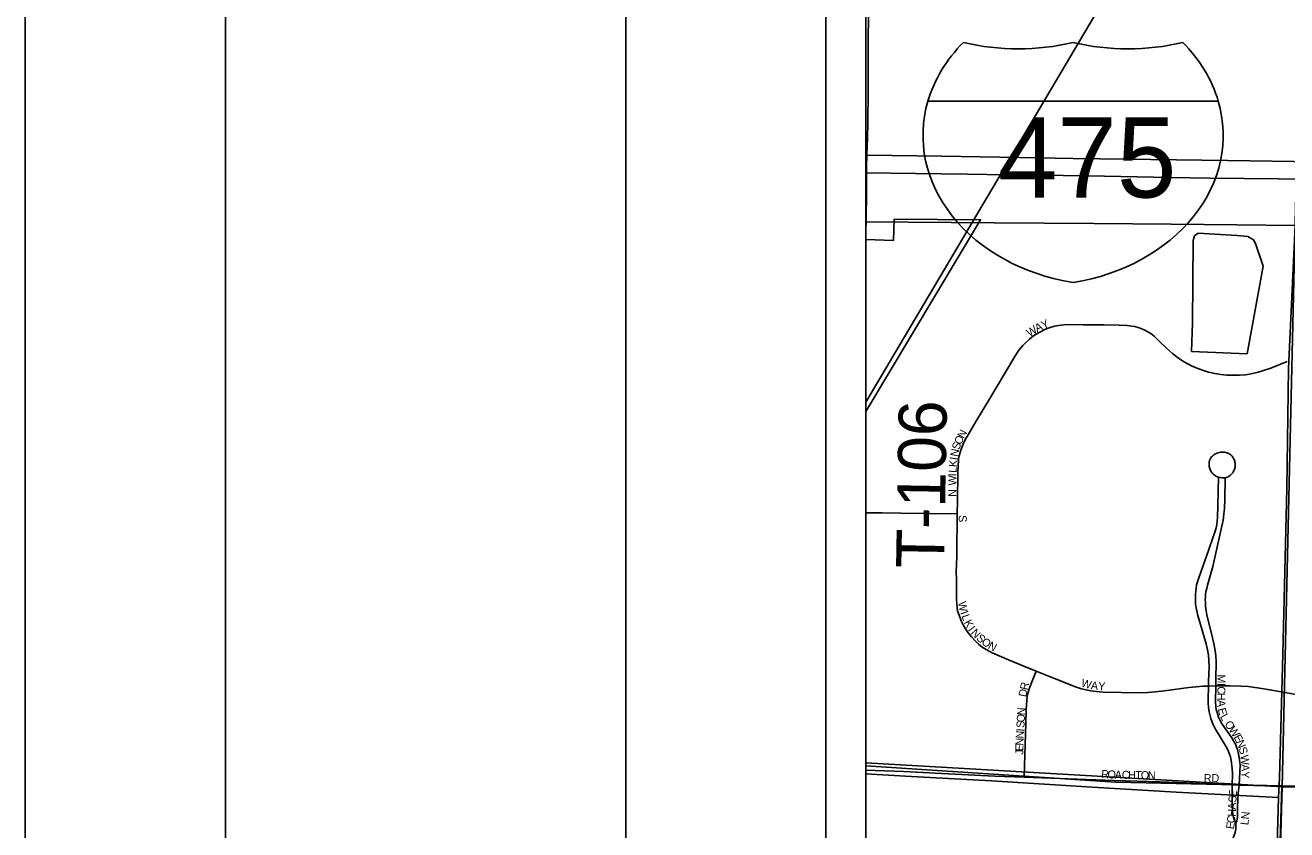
# Model space of a CAD drawing. Extents: x -5.6 to 34, y 0 to 22.
# Drawn here: x 0 to 3.152, y 16.752 to 18.761 of the extents above; entities that cross this region are included whole.
import ezdxf

# ---------------------------------------------------------------- set-up
doc = ezdxf.new("R2010")
doc.units = 0
for name, color, linetype in [('GM_X_City_Street', 7, 'Continuous'), ('GM_X_City_Street_Text', 7, 'Continuous'), ('GM_X_Corporation', 7, 'Continuous'), ('GM_X_County_Road', 7, 'Continuous'), ('GM_X_Interstate_Location', 7, 'Continuous'), ('GM_X_Interstate_Route', 7, 'Continuous'), ('GM_X_Interstate_Shield', 7, 'Continuous'), ('GM_X_Minor_Lake', 7, 'Continuous'), ('GM_X_Minor_River', 7, 'Continuous'), ('GM_X_Rail_Line', 7, 'Continuous'), ('GM_X_Section', 7, 'Continuous'), ('GM_X_Township', 7, 'Continuous'), ('GM_X_Township_Road', 7, 'Continuous'), ('GM_X_Township_Road_Text', 7, 'Continuous'), ('SH_Border', 7, 'Continuous'), ('SH_Cut_Line', 7, 'Continuous'), ('SH_Data', 7, 'Continuous')]:
    doc.layers.add(name, color=color, linetype=linetype)

msp = doc.modelspace()

# ---------------------------------------------------------------- linework, layer by layer
at = {"layer": 'GM_X_City_Street'}
for points in [[(2.1056, 18.6334), (2.1057, 18.6718), (2.1062, 18.7298), (2.107, 18.7758), (2.1077, 18.8077), (2.1078, 18.8277)], [(2.1038, 18.4756), (2.1046, 18.5206), (2.1054, 18.5934)], [(2.1, 18.2364), (2.1016, 18.3334), (2.1019, 18.3922), (2.102, 18.4075), (2.1027, 18.4361), (2.1036, 18.4614), (2.1038, 18.4756)], [(2.3282, 17.541), (2.3291, 17.5724), (2.3301, 17.6438), (2.3307, 17.6628), (2.3312, 17.6714), (2.3318, 17.6777), (2.3334, 17.6857), (2.3345, 17.6909), (2.3378, 17.7019), (2.3428, 17.7146), (2.3488, 17.7267), (2.3554, 17.738), (2.3739, 17.7697), (2.4126, 17.8329), (2.4438, 17.8858), (2.4749, 17.9378), (2.4826, 17.9494), (2.492, 17.9607), (2.4983, 17.9671), (2.5091, 17.977), (2.5159, 17.9825), (2.5239, 17.9882), (2.5364, 17.9952), (2.5492, 18.0015), (2.5601, 18.0057), (2.5712, 18.009), (2.5813, 18.0111), (2.5942, 18.0126), (2.6085, 18.0132), (2.6426, 18.0129), (2.6952, 18.0124), (2.7332, 18.0118), (2.7528, 18.0108), (2.7644, 18.0096), (2.7719, 18.008), (2.7831, 18.0047), (2.7952, 18), (2.8044, 17.9954), (2.812, 17.9906), (2.82, 17.9842), (2.8312, 17.9733), (2.8514, 17.9543), (2.8661, 17.9411), (2.8775, 17.9321), (2.8895, 17.9237), (2.9009, 17.9169), (2.915, 17.9097), (2.9296, 17.9033), (2.9432, 17.8983), (2.956, 17.8946), (2.9715, 17.8912), (2.9872, 17.8887), (3.0017, 17.8872), (3.0175, 17.8867), (3.0334, 17.8871), (3.0483, 17.888), (3.0629, 17.8902), (3.0797, 17.894), (3.0937, 17.8982), (3.1116, 17.9045), (3.1524, 17.9211)], [(2.9813, 17.6318), (2.9787, 17.6328), (2.9761, 17.634), (2.9733, 17.6355), (2.9709, 17.6369), (2.9686, 17.6388), (2.9668, 17.6405), (2.9651, 17.6426), (2.9636, 17.6445), (2.9623, 17.6466), (2.9612, 17.6488), (2.9601, 17.6511), (2.9591, 17.6536), (2.9584, 17.6561), (2.9578, 17.659), (2.9575, 17.6621), (2.9574, 17.665), (2.9575, 17.6678), (2.958, 17.6708), (2.9587, 17.6734), (2.9596, 17.6758), (2.961, 17.6784), (2.9622, 17.6805), (2.9638, 17.6826), (2.9658, 17.6847), (2.9677, 17.6863), (2.9696, 17.6879), (2.9717, 17.6893), (2.9741, 17.6906), (2.9767, 17.6918), (2.98, 17.6931), (2.9832, 17.6939), (2.9862, 17.6945), (2.9895, 17.6949), (2.993, 17.6949), (2.996, 17.6947), (2.9993, 17.694), (3.002, 17.6931), (3.0044, 17.6922), (3.007, 17.6908), (3.0095, 17.6893), (3.0115, 17.6877), (3.0133, 17.6861), (3.015, 17.6843), (3.0164, 17.6824), (3.0175, 17.6806), (3.0188, 17.6785), (3.0199, 17.6761), (3.0208, 17.6737), (3.0216, 17.6714), (3.0221, 17.6692), (3.0225, 17.6673), (3.0228, 17.6654), (3.0229, 17.6633), (3.0229, 17.6613), (3.0228, 17.6591), (3.0224, 17.6568), (3.022, 17.6546), (3.0212, 17.6522), (3.0201, 17.6495), (3.0192, 17.6476), (3.018, 17.6456), (3.017, 17.6439), (3.0159, 17.6423), (3.0147, 17.6408), (3.0134, 17.6393), (3.0118, 17.6376), (3.0101, 17.6361), (3.0079, 17.6346), (3.0059, 17.6334), (3.004, 17.6324), (3.0026, 17.6318), (3.0007, 17.6314), (2.9975, 17.6307)], [(2.9562, 17.1105), (2.9564, 17.1223), (2.9574, 17.1577), (2.9572, 17.1748), (2.9561, 17.1879), (2.9539, 17.2008), (2.9501, 17.2161), (2.9357, 17.2639), (2.9293, 17.2866), (2.9259, 17.302), (2.9239, 17.3149), (2.9234, 17.3238), (2.9232, 17.3313), (2.9234, 17.3394), (2.9241, 17.3478), (2.9249, 17.3551), (2.9264, 17.3631), (2.9284, 17.3707), (2.9317, 17.3803), (2.9566, 17.4511), (2.966, 17.4784), (2.9716, 17.4945), (2.9748, 17.5058), (2.9765, 17.5135), (2.9778, 17.5226), (2.9785, 17.5318), (2.9792, 17.5593), (2.9813, 17.6318)], [(2.9744, 17.111), (2.9746, 17.1279), (2.975, 17.1712), (2.9744, 17.1856), (2.973, 17.1986), (2.9703, 17.2128), (2.964, 17.2383), (2.9548, 17.2739), (2.9515, 17.288), (2.9499, 17.2983), (2.9488, 17.3101), (2.9484, 17.3181), (2.948, 17.3265), (2.9482, 17.3327), (2.9487, 17.3391), (2.9497, 17.3463), (2.9515, 17.3541), (2.9537, 17.3624), (2.9666, 17.4091), (2.9787, 17.4616), (2.9846, 17.4872), (2.9889, 17.5061), (2.9913, 17.5169), (2.9927, 17.524), (2.9936, 17.5311), (2.9946, 17.5405), (2.9957, 17.5539), (2.9969, 17.5767), (2.9975, 17.6307)], [(2.9975, 17.6307), (2.9947, 17.6305), (2.9918, 17.6306), (2.9893, 17.6308), (2.9864, 17.631), (2.984, 17.6314), (2.9813, 17.6318)], [(2.1, 17.5432), (2.1408, 17.5428), (2.1874, 17.5418), (2.2486, 17.5414), (2.3275, 17.5409), (2.3282, 17.541)], [(2.3282, 17.541), (2.328, 17.5096), (2.3275, 17.4714), (2.327, 17.4356), (2.3265, 17.4126), (2.326, 17.3955), (2.3261, 17.3773), (2.3261, 17.3602), (2.3261, 17.346), (2.3261, 17.3293), (2.3271, 17.3137), (2.3293, 17.2981), (2.3328, 17.2871), (2.338, 17.2737), (2.343, 17.2632), (2.3488, 17.2531), (2.3554, 17.2436), (2.3636, 17.2335), (2.3733, 17.223), (2.3818, 17.215), (2.391, 17.2079), (2.4006, 17.2014), (2.4153, 17.1937), (2.4329, 17.1859), (2.4565, 17.1763), (2.4946, 17.1602), (2.5252, 17.1473)], [(2.4956, 16.8827), (2.4965, 16.9109), (2.4981, 16.9647), (2.4999, 17.0172), (2.5009, 17.0513), (2.5022, 17.0749), (2.5033, 17.084), (2.5048, 17.0917), (2.5072, 17.1006), (2.5119, 17.1142), (2.5252, 17.1473)], [(2.5252, 17.1473), (2.571, 17.1293), (2.6237, 17.1086), (2.6386, 17.1036), (2.65, 17.1006), (2.6616, 17.0983), (2.6759, 17.0965), (2.6929, 17.0955), (2.7388, 17.0945), (2.7821, 17.0939), (2.8044, 17.0944), (2.8227, 17.0956), (2.8462, 17.0981), (2.9072, 17.1067), (2.9252, 17.1087), (2.942, 17.11), (2.9562, 17.1105)], [(3.0151, 16.8637), (3.0157, 16.8901), (3.0151, 16.9046), (3.0136, 16.9177), (3.0123, 16.9255), (3.0106, 16.9335), (3.0083, 16.9403), (3.0059, 16.9467), (3.0014, 16.9561), (2.9977, 16.9628), (2.9927, 16.9711), (2.9798, 16.9918), (2.9746, 17.0007), (2.9701, 17.0092), (2.9671, 17.0151), (2.964, 17.0228), (2.9618, 17.0295), (2.9598, 17.0363), (2.9576, 17.0457), (2.9562, 17.0572), (2.9551, 17.0684), (2.9553, 17.083), (2.9561, 17.1053), (2.9562, 17.1105)], [(2.9562, 17.1105), (2.9744, 17.111)], [(3.0326, 16.863), (3.0348, 16.9127), (3.0336, 16.9258), (3.0316, 16.9374), (3.03, 16.9448), (3.0293, 16.9475), (3.0281, 16.9519), (3.0263, 16.9582), (3.0241, 16.9637), (3.0197, 16.9722), (3.0145, 16.9812), (2.9904, 17.0156), (2.985, 17.0246), (2.9811, 17.0329), (2.9781, 17.0416), (2.9765, 17.0468), (2.9754, 17.0518), (2.9744, 17.0591), (2.9738, 17.0714), (2.9744, 17.111)], [(2.9744, 17.111), (2.9777, 17.1111), (3.0105, 17.1112), (3.0367, 17.1104), (3.0562, 17.109), (3.0717, 17.1065), (3.0782, 17.1057), (3.1093, 17.1011), (3.152, 17.0933), (3.1883, 17.0871), (3.2117, 17.0836), (3.2483, 17.0793), (3.2628, 17.0783), (3.2812, 17.0779), (3.3076, 17.0782), (3.3128, 17.0781), (3.3234, 17.0782), (3.3533, 17.078), (3.3691, 17.0783)], [(2.1, 16.9006), (2.1941, 16.8973), (2.2436, 16.8947), (2.2733, 16.8933), (2.4224, 16.8856), (2.4956, 16.8827)], [(2.4956, 16.8827), (2.6289, 16.8775), (2.7207, 16.8747), (2.8346, 16.8715), (2.9022, 16.8689), (2.9334, 16.8672), (2.9776, 16.8651), (3.0135, 16.8638), (3.0151, 16.8637)], [(3.0242, 16.7668), (3.0198, 16.7778), (3.0187, 16.7818), (3.0177, 16.7864), (3.0169, 16.7915), (3.016, 16.7997), (3.0152, 16.8127), (3.0151, 16.8475), (3.0151, 16.8637)], [(3.0151, 16.8637), (3.0326, 16.863)], [(3.0242, 16.7668), (3.0264, 16.7741), (3.0274, 16.7787), (3.0282, 16.7844), (3.0286, 16.7893), (3.0288, 16.7952), (3.0288, 16.8071), (3.0293, 16.8252), (3.0302, 16.8432), (3.0326, 16.863)], [(3.1051, 16.8615), (3.1386, 16.8609), (3.2435, 16.8604), (3.2729, 16.86), (3.3546, 16.8585), (3.3653, 16.8582)], [(2.9966, 16.6798), (3.0005, 16.6891), (3.014, 16.7221), (3.0195, 16.7357), (3.0223, 16.7448), (3.0233, 16.7491), (3.0242, 16.7546), (3.0246, 16.7584), (3.0246, 16.7617), (3.0242, 16.7668)]]:
    msp.add_lwpolyline(points, dxfattribs=at)
at = {"layer": 'GM_X_Corporation'}
msp.add_lwpolyline([(3.2277, 20.9), (2.1, 20.9), (2.1, 18.226), (2.1688, 18.2231), (2.1708, 18.2767), (2.3867, 18.2751), (2.1, 17.7957), (2.1, 16.1715), (2.1566, 16.1698), (2.1557, 16.0644), (2.1, 16.0648), (2.1, 15.8951), (2.1803, 15.8911), (2.1794, 15.8126), (2.1472, 15.8117), (2.1446, 15.7502), (2.1, 15.7518), (2.1, 15.0823), (2.1322, 15.0813), (2.127, 14.9352), (2.1, 14.9372), (2.1, 14.8511)], dxfattribs=at)
at = {"layer": 'GM_X_County_Road'}
msp.add_lwpolyline([(3.0326, 16.863), (3.1051, 16.8615)], dxfattribs=at)
at = {"layer": 'GM_X_Interstate_Route'}
for points in [[(4.2499, 18.4038), (4.241, 18.404), (4.224, 18.4042), (4.2182, 18.4042), (4.0987, 18.4063), (4.0606, 18.4069), (3.9543, 18.4086), (3.76, 18.4114), (3.5567, 18.4135), (3.5473, 18.4136), (3.4449, 18.4151), (3.3175, 18.4175), (3.223, 18.4193), (3.1154, 18.4213), (3.0038, 18.4231), (2.8121, 18.4255), (2.7491, 18.4264), (2.6178, 18.428), (2.4839, 18.4301), (2.3854, 18.4317), (2.2896, 18.4334), (2.1649, 18.4352), (2.1027, 18.4361), (2.1, 18.4362)], [(3.1955, 18.3766), (3.1298, 18.3772), (2.9605, 18.3791), (2.8594, 18.3808), (2.6966, 18.3835), (2.5929, 18.3854), (2.4511, 18.3872), (2.3539, 18.3884), (2.224, 18.3906), (2.1019, 18.3922), (2.1, 18.3922)]]:
    msp.add_lwpolyline(points, dxfattribs=at)
at = {"layer": 'GM_X_Interstate_Shield'}
msp.add_line((2.9804, 18.5711), (2.2552, 18.5711), dxfattribs=at)
msp.add_line((2.9804, 18.5711), (2.2552, 18.5711), dxfattribs=at)
for centre, start_param, end_param in [((2.7115, 18.4854), 2.47259, 2.911027), ((2.4808, 19.0766), 4.415841, 5.008937), ((2.7547, 19.0766), 4.415841, 5.008937), ((2.524, 18.4854), 0.230566, 0.669003), ((2.7115, 18.4854), 2.911027, 4.511031), ((2.524, 18.4854), 4.913747, 6.513751)]:
    msp.add_ellipse(centre, major_axis=(0.4688, 0), ratio=0.8, start_param=start_param, end_param=end_param, dxfattribs=at)
at = {"layer": 'GM_X_Minor_Lake'}
msp.add_line((2.9161, 18.0174), (2.9135, 17.9461), dxfattribs=at)
msp.add_lwpolyline([(2.9135, 17.9461), (3.0523, 17.9403), (3.0928, 18.1591), (3.0734, 18.2157), (3.0688, 18.2246), (3.0546, 18.233), (3.0275, 18.2353), (2.9303, 18.2416), (2.9213, 18.2346), (2.9179, 18.2235), (2.9161, 18.0174)], dxfattribs=at)
at = {"layer": 'GM_X_Minor_River'}
for points in [[(2.1, 18.2695), (2.4207, 18.2669), (2.6706, 18.2656), (2.863, 18.2641), (3.0266, 18.2625), (3.1727, 18.2606)], [(3.1727, 18.2606), (3.156, 17.9033), (3.1519, 17.6042), (3.1419, 17.1897), (3.1336, 16.8819), (3.1308, 16.8323), (3.1221, 16.5076), (3.1169, 16.2286), (3.1032, 15.8929), (3.0921, 15.5667), (3.0838, 15.1603), (3.0776, 14.8396), (3.0715, 14.6841), (2.7803, 14.6952), (2.5171, 14.7048), (2.3034, 14.7157)], [(3.1308, 16.8323), (2.8756, 16.8457), (2.6652, 16.8581), (2.414, 16.8738), (2.1988, 16.8855), (2.1, 16.8913)]]:
    msp.add_lwpolyline(points, dxfattribs=at)
at = {"layer": 'GM_X_Rail_Line'}
msp.add_lwpolyline([(2.1, 17.8198), (3.0599, 19.4414), (3.6284, 20.3994)], dxfattribs=at)
at = {"layer": 'GM_X_Section'}
for points in [[(2.1, 19.0324), (2.1, 16.9188), (3.1401, 16.8587), (3.1889, 18.9888), (2.7758, 19.0054), (2.2725, 19.0255)], [(3.1889, 18.9888), (5.3166, 18.9352), (5.2895, 16.8144), (3.1401, 16.8587)], [(2.1, 16.9188), (2.1, 14.755), (3.0791, 14.7168), (3.1401, 16.8587)], [(3.1401, 16.8587), (5.2895, 16.8144), (5.2575, 14.6921), (3.0791, 14.7168)]]:
    msp.add_lwpolyline(points, close=True, dxfattribs=at)
at = {"layer": 'GM_X_Township'}
for points in [[(3.0636, 14.1), (8.9, 14.1), (8.9, 20.9), (2.1, 20.9), (2.1, 16.9108), (2.7242, 16.8707), (3.1388, 16.8616), (3.0745, 14.7121)], [(2.1, 16.9108), (2.1, 14.1), (3.0636, 14.1), (3.0745, 14.7121), (3.1388, 16.8616), (2.7242, 16.8707)]]:
    msp.add_lwpolyline(points, close=True, dxfattribs=at)
at = {"layer": 'GM_X_Township_Road'}
msp.add_lwpolyline([(2.1054, 18.5934), (2.1055, 18.606), (2.1056, 18.6334)], dxfattribs=at)
at = {"layer": 'SH_Border'}
for points in [[(0.5, 21.5), (1.5, 21.5), (1.5, 0.5), (0.5, 0.5)], [(1.5, 21.5), (33.5, 21.5), (33.5, 0.5), (1.5, 0.5)]]:
    msp.add_lwpolyline(points, close=True, dxfattribs=at)
at = {"layer": 'SH_Cut_Line'}
msp.add_lwpolyline([(0, 0), (34, 0), (34, 22), (0, 22)], close=True, dxfattribs=at)
at = {"layer": 'SH_Data'}
for p, q in [((2, 21), (2, 14)), ((2.1, 20.9), (2.1, 14.1))]:
    msp.add_line(p, q, dxfattribs=at)

# ---------------------------------------------------------------- texts
at = {"layer": 'GM_X_City_Street_Text'}
for s, rotation, p in [('W', 32.2584, (2.5089, 17.9819)), ('A', 25.6071, (2.5277, 17.9938)), ('Y', 24.6881, (2.5435, 18.0014)), ('N', 62.2913, (2.3452, 17.7271)), ('S', 71.5132, (2.3332, 17.6988)), ('O', 63.6109, (2.3374, 17.7114)), ('I', 81.3136, (2.3287, 17.6737)), ('N', 78.7801, (2.3299, 17.6821)), ('L', 87.2399, (2.3265, 17.6426)), ('K', 84.8352, (2.3271, 17.6565)), ('W', 89.731, (2.3263, 17.6112)), ('I', 89.7279, (2.3264, 17.634)), ('N', 90, (2.3263, 17.583)), ('S', 270, (2.3321, 17.5373)), ('W', 280.2417, (2.3304, 17.3198)), ('I', 289.9386, (2.3354, 17.2938)), ('L', 290.1397, (2.3385, 17.2854)), ('K', 297.1994, (2.3444, 17.2697)), ('I', 306.9464, (2.3544, 17.2509)), ('N', 312.4994, (2.361, 17.2423)), ('S', 318.0789, (2.3745, 17.2278)), ('O', 325.0477, (2.387, 17.2167)), ('N', 331.2446, (2.4034, 17.2054)), ('R', 76.9945, (2.5039, 17.0991)), ('W', 344.4057, (2.636, 17.1096)), ('A', 353.7401, (2.6615, 17.1027)), ('Y', 355.4431, (2.6797, 17.1008)), ('M', 270.0911, (2.978, 17.1395)), ('I', 270.1045, (2.978, 17.1184)), ('D', 79.2259, (2.5006, 17.0821)), ('C', 270.0972, (2.9781, 17.1096)), ('H', 270.0874, (2.9781, 17.0937)), ('N', 86.6322, (2.4977, 17.037)), ('A', 270.9054, (2.9781, 17.0758)), ('E', 283.857, (2.979, 17.0533)), ('S', 86.6383, (2.4959, 17.0054)), ('O', 86.6322, (2.4967, 17.0194)), ('L', 298.1265, (2.9843, 17.0346)), ('O', 304.8113, (2.9952, 17.0156)), ('N', 86.6759, (2.4943, 16.979)), ('I', 86.631, (2.4953, 16.9966)), ('W', 304.5622, (3.0052, 17.0012)), ('E', 298.9485, (3.0179, 16.9828)), ('E', 89.6448, (2.4935, 16.9476)), ('N', 87.6605, (2.4936, 16.9615)), ('N', 292.4467, (3.0245, 16.971)), ('S', 285.9979, (3.031, 16.9553)), ('J', 89.9126, (2.4935, 16.9389)), ('W', 274.9326, (3.0358, 16.9376)), ('R', 357.0115, (2.6876, 16.881)), ('O', 357.3357, (2.7035, 16.8802)), ('A', 358.7092, (2.7216, 16.8794)), ('C', 359.008, (2.7393, 16.879)), ('H', 358.9945, (2.7551, 16.8787)), ('T', 359.0279, (2.7728, 16.8784)), ('O', 359.0164, (2.7868, 16.8781)), ('N', 358.9945, (2.8044, 16.8778)), ('A', 270.1968, (3.0378, 16.9152)), ('Y', 270, (3.0378, 16.8977)), ('RD', 0, (2.9443, 16.8705)), ('S', 86.6383, (3.0255, 16.8189)), ('E', 85.4882, (3.0263, 16.8328)), ('H', 86.4798, (3.0234, 16.7837)), ('A', 86.6374, (3.0245, 16.8013)), ('E', 81.281, (3.0193, 16.752)), ('C', 83.4533, (3.0215, 16.7668)), ('L', 82.6852, (3.0553, 16.7622)), ('N', 84.8138, (3.0571, 16.7769))]:
    msp.add_text(s, height=0.02, rotation=rotation, dxfattribs=at).set_placement(p)
at = {"layer": 'GM_X_Interstate_Location'}
for s in ['-', '.', ',']:
    msp.add_text(s, height=0.0004, dxfattribs=at).set_placement((2.6177, 18.4303))
msp.add_text('475', height=0.0004, rotation=0, dxfattribs=at).set_placement((2.4955, 18.3475))
at = {"layer": 'GM_X_Interstate_Shield'}
msp.add_text('475', height=0.2, dxfattribs=at).set_placement((2.4296, 18.3305))
at = {"layer": 'GM_X_Township_Road_Text'}
msp.add_text('T-106', height=0.12, rotation=88.9978, dxfattribs=at).set_placement((2.2953, 17.4038))

doc.saveas('drawing.dxf')
